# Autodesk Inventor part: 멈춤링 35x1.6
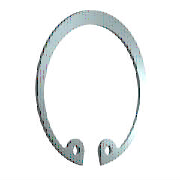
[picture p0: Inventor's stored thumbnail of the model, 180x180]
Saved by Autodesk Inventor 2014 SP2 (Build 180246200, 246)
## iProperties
IsCustomPart: 1
Created: 2012-02
Part Number: 멈춤링 35x1.6
Material: 강철, 연강
Description: 리테이닝 링(C형)
Document SubType Name: Modeling
Standard: KS B 1336
Designer: mduedu
Standards Organization: KS
Language: ko-KR
Size Designation: 35x1.6
Categories: <MemberInstance><Categories><Category DisplayName="샤프트 부품" InternalName="7f7aeb1f-a693-4053-b835-cee3144e0d98" Mnemonic="SHFT"><Category DisplayName="써클립" Inter
Density: 1 g/cm^3
Appearance: 파란색 - 벽 페인트 - 광택
Author: mduedu
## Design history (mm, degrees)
sketch "스케치1"
  geometry: L1 (0, 15.113)-(0, -73.177) reference; L2 (-45.5, 0)-(45.5, 0) reference; L3 (-4.964, 1)-(1.502, 1); L4 (0, -2.5)-(-5.307, -2.5); L5 (0, -17.5)-(-8.583, -33.888); L6 (-8.583, -33.888)-(-21.772, -26.981); L7 (-7.377, -31.585)-(-17.631, -26.214); L8 (-5.162, -32.745)-(-6.29, -34.898); L9 (5.162, -32.745)-(6.29, -34.898); C1 r 1.25 at (-7.377, -31.585); C2 r 1.25 at (7.377, -31.585); A1 r 15.875 centre (0, -18.375) between (11.82, -28.972) and (-11.82, -28.972); A2 r 18.5 centre (0, -17.5) between (6.29, -34.898) and (-6.29, -34.898); A3 r 2.5 centre (-7.377, -31.585) between (-5.162, -32.745) and (-8.668, -29.444); A4 r 2.5 centre (-9.959, -27.303) between (-11.82, -28.972) and (-8.668, -29.444); A5 r 2.5 centre (9.959, -27.303) between (8.668, -29.444) and (11.82, -28.972); A6 r 2.5 centre (7.377, -31.585) between (8.668, -29.444) and (5.162, -32.745); 3 further points
  constraints: 15 point on circle, 14 end point, 9 symmetric about line, 8 centre point, 6 tangent, 4 coincident, 4 point on line, 3 perpendicular, 1 parallel, 4 other
  dimensions: "d8" = 0.875 distance of A1.centre L5.start (= 0.25 x SRB1); "d38" = 3.5 distance between parallel lines of L4 L3 (= SRB1); "d39" = 17.5 distance from line of L5.start L2 (= 0.5 x WD); "d43" = 18.5 radius of A2 (= 0.5 x ND); "d45" = 2.6 distance between parallel lines of L7 L6 (= 0.5 x SRB2); "d46" = 2.5 radius of A4 (= SD5); "d47" = 6.29 distance from line of L1 L8.end (= 0.17 x ND); "d48" = 2.5 diameter of C1 (= SD5); "d49" = 2.5 radius of A3 (= SD5)
extrude "본체" new body sketch "스케치1" distance "d2" = 1.6 (= SD); taper "d3" = 0 deg
workaxis "Work Axis1"
workaxis "Work Axis2"
workplane "Work Plane1"
body "Solid1"
other parameters: "WD" = 35 [user parameter; used in 3 equation terms], "SD" = 1.6 [user parameter; used in 1 equation term], "SRB1" = 3.5 [user parameter; used in 2 equation terms], "ND" = 37 [user parameter; used in 2 equation terms], "SRB2" = 5.2 [user parameter; used in 1 equation term], "SD5" = 2.5 [user parameter; used in 3 equation terms], "d50" = 0, "d51" = 0, "d52" = 0, "d53" = 0, "WDMIN" = 34 [user parameter], "SD6" = 37.8 [user parameter], "WDMAX" = 35 (= WD) [user parameter], "NND" = 35 (= WD) [user parameter]
